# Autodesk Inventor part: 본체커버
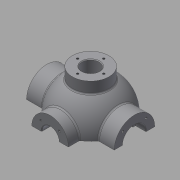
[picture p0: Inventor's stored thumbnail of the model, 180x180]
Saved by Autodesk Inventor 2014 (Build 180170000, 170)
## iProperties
Created: 2015-12
Part Number: 본체커버
Material: 알루미늄 6061
Document SubType Name: Modeling
Designer: mduedu
Density: 1 g/cm^3
Mass: 574.351 g
Surface Area: 450.515 cm^2
Volume: 211.938 cm^3
Appearance: 알루미늄 - 평지
Author: mduedu
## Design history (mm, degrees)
sketch "스케치1"
  geometry: L1 (-53, 0)-(53, 0); A1 r 53 centre (0, 0) between (53, 0) and (-53, 0); 2 further points
  constraints: 2 coincident, 2 end point, 2 point on circle, 1 centre point, 1 horizontal, 1 midpoint
  dimensions: "d0" = 53 radius of A1
revolve "회전1" sketch "스케치1" stored, may be unused: angle "d2" = 90 deg
feature "쉘1" dims "d11" = 10
node "작업 평면1"
sketch "스케치2"
  geometry: C1 r 31 at (0, 0); 1 further point
  constraints: 1 centre point, 1 coincident
  dimensions: "d4" = 62 diameter of C1
extrude "돌출1" join sketch "스케치2" stored distance "d5" = 10; taper "d6" = 0 deg
node "작업 평면2"
sketch "스케치3"
  geometry: C1 r 28 at (0, 0); 1 further point
  constraints: 1 centre point, 1 coincident
  dimensions: "d8" = 56 diameter of C1
extrude "돌출2" join sketch "스케치3" stored distance "d9" = 10; taper "d10" = 0 deg
hole "구멍1" diameter "d14" = 35; stored, may be unused: countersink angle "d18" = 90 deg, drill point angle "d20" = 0 deg; dims "d12" = 10, "d13" = 10, "d15" = 6, "d16" = 4, "d17" = 2, "d19" = 16
hole "구멍2" diameter "d23" = 27; stored, may be unused: countersink angle "d27" = 90 deg, drill point angle "d29" = 0 deg; dims "d21" = 10, "d22" = 10, "d24" = 6, "d25" = 4, "d26" = 2, "d28" = 16
fillet "모깎기1" dims "d30" = 0.3
hole "구멍3" diameter "d33" = 26; stored, may be unused: countersink angle "d37" = 90 deg, drill point angle "d39" = 0 deg; dims "d31" = 10, "d32" = 10, "d34" = 6, "d35" = 4, "d36" = 2, "d38" = 16
chamfer "모따기1" distance "d40" = 1; stored, may be unused: second distance "d41" = 2, angle "d42" = 45 deg
sketch "스케치4"
  geometry: L1 (0, 0)-(0, -25); L2 (0, 0)-(-17.678, -17.678); A1 r 25 centre (0, 0) between (-17.678, -17.678) and (0, -25); 1 further point
  constraints: 4 end point, 2 point on circle, 1 centre point, 1 coincident, 1 vertical
  dimensions: "d43" = 50 diameter of A1; "d47" = 45 deg angle of L1 L2
hole "구멍4" sketch "스케치4" at (-17.678, -17.678) diameter "d49" = 3.242; stored, may be unused: countersink angle "d53" = 90 deg, drill point angle "d55" = 118 deg; dims "d50" = 11, "d51" = 4, "d52" = 2, "d54" = 13
sketch "스케치5"
  geometry: L1 (0, 0)-(0, -20); L2 (0, 0)-(-14.142, -14.142); A1 r 20 centre (0, 0) between (0, -20) and (-14.142, -14.142); 2 further points
  constraints: 4 end point, 2 coincident, 2 point on circle, 1 centre point, 1 vertical
  dimensions: "d59" = 40 diameter of A1; "d65" = 45 deg angle of L1 L2
hole "구멍5" sketch "스케치5" at (-14.142, -14.142) diameter "d67" = 3.242; stored, may be unused: countersink angle "d71" = 90 deg, drill point angle "d73" = 118 deg; dims "d68" = 8, "d69" = 4, "d70" = 2, "d72" = 10
node "작업 평면3"
sketch "스케치6"
  geometry: C1 r 65 at (0, 0); 1 further point
  constraints: 1 centre point, 1 coincident
  dimensions: "d78" = 130 diameter of C1
extrude "돌출3" join sketch "스케치6" distance "d80" = 10; taper "d81" = 0 deg
sketch "스케치7"
  geometry: C1 r 20 at (0, 0); 1 further point
  constraints: 1 centre point, 1 coincident
  dimensions: "d82" = 40 diameter of C1
extrude "돌출4" join sketch "스케치7" stored distance "d84" = 10; taper "d85" = 0 deg
sketch "스케치8"
  geometry: 2 further points
  constraints: 1 coincident
hole "구멍6" sketch "스케치8" at (0, 0) diameter "d86" = 20; stored, may be unused: countersink angle "d90" = 90 deg, drill point angle "d92" = 118 deg; dims "d87" = 7, "d88" = 40, "d89" = 5, "d91" = 10
fillet "모깎기2" dims "d93" = 0.3
sketch "스케치9"
  geometry: L1 (65, -75)-(-65, -75) reference; L2 (-45, -75)-(-38.245, -36.692); A1 r 53 centre (0, 0) between (42.988, 31) and (42.988, -31) reference; 1 further point
  constraints: 2 end point, 1 point on circle, 1 point on line
  dimensions: "d94" = 45 horizontal distance of L2.start point (0, 0); "d95" = 80 deg angle of L2 L1
feature "리브1" sketch "스케치9" dims "d96" = 1, "d97" = 8, "d98" = 0, "d99" = 0, "d100" = 1, "d101" = 1
sketch "스케치10"
  geometry: L1 (0, 0)-(0, -55); L2 (0, 0)-(-38.891, -38.891); A1 r 55 centre (0, 0) between (0, -55) and (-38.891, -38.891); 2 further points
  constraints: 4 end point, 2 coincident, 2 point on circle, 1 centre point, 1 vertical
  dimensions: "d105" = 110 diameter of A1; "d107" = 45 deg angle of L1 L2
hole "구멍7" sketch "스케치10" at (-38.891, -38.891) diameter "d109" = 10; stored, may be unused: countersink angle "d113" = 90 deg, drill point angle "d115" = 118 deg; dims "d110" = 7, "d111" = 40, "d112" = 5, "d114" = 10
fillet "모깎기3" dims "d120" = 3
fillet "모깎기4" dims "d121" = 3, "d122" = 3
fillet "모깎기5" dims "d123" = 3
fillet "모깎기6" dims "d124" = 3
sketch "스케치11"
  geometry: C1 r 5 at (-38.891, 38.891) reference; C2 r 5 at (38.891, 38.891) reference; C3 r 5 at (38.891, -38.891) reference; C4 r 5 at (-38.891, -38.891) reference; C5 r 20 at (0, 0) reference; C6 r 65 at (0, 0) reference; 1 further point
  constraints: 3 other
feature "엠보싱1" sketch "스케치11" dims "d125" = 0.5, "d126" = 0
sketch "스케치12"
  geometry: L1 (0, 100)-(0, -100); L2 (0, 100)-(-150, 100); L3 (-150, 100)-(-150, -100); L4 (-150, -100)-(0, -100); 2 further points
  constraints: 8 end point, 3 perpendicular, 1 coincident, 1 midpoint, 1 vertical
  dimensions: "d127" = 200 distance of L2.end L3.end; "d129" = 150 distance of L3.end L1.end
extrude "돌출5" cut sketch "스케치12" stored distance "d130" = 10; taper "d131" = 0 deg
sketch "스케치13"
  geometry: C1 r 7 at (0, -53); A1 r 53 centre (0, 0) between (-42.113, -32.179) and (42.113, -32.179) reference; 1 further point
  constraints: 1 centre point, 1 point on circle
  dimensions: "d132" = 14 diameter of C1
extrude "돌출6" join sketch "스케치13" distance "d133" = 5; taper "d134" = 0 deg
sketch "스케치14"
  geometry: C1 r 7 at (0, 0) reference; 1 further point
extrude "돌출7" cut sketch "스케치14" stored distance "d135" = 5; taper "d136" = 0 deg
sketch "스케치15"
  geometry: C1 r 2.25 at (0, 53); A1 r 7 centre (0, 53) between (6.965, 52.302) and (-6.965, 52.302) reference; 1 further point
  constraints: 1 centre point, 1 coincident
  dimensions: "d139" = 4.5 diameter of C1
extrude "돌출8" cut sketch "스케치15" stored distance "d141" = 5; taper "d142" = 0 deg
fillet "모깎기7" dims "d143" = 3
fillet "모깎기8" dims "d144" = 1
fillet "모깎기9" dims "d145" = 1
fillet "모깎기10" dims "d146" = 1
node "작업 평면4"
sketch "스케치16"
  geometry: C1 r 28 at (0, 0); 1 further point
  constraints: 1 centre point, 1 coincident
  dimensions: "d148" = 56 diameter of C1
extrude "돌출9" join sketch "스케치16" stored distance "d150" = 5; taper "d151" = 0 deg
hole "구멍8" diameter "d154" = 26; stored, may be unused: countersink angle "d158" = 90 deg, drill point angle "d160" = 118 deg; dims "d152" = 10, "d153" = 10, "d155" = 6, "d156" = 4, "d157" = 2, "d159" = 8
sketch "스케치17" dims "d161" = 40
  geometry: 3 further points
  constraints: 2 vertical alignment, 1 coincident, 2 other
hole "구멍9" sketch "스케치17" at (0, 20) diameter "d163" = 3.242; stored, may be unused: countersink angle "d167" = 90 deg, drill point angle "d169" = 118 deg; dims "d164" = 8, "d165" = 4, "d166" = 2, "d168" = 10
fillet "모깎기11" dims "d173" = 3
chamfer "모따기2" distance "d174" = 1; stored, may be unused: second distance "d175" = 2, angle "d176" = 45 deg
node "솔리드1"
mirror "대칭1"
mirror "대칭2"
pattern_circular "원형 패턴1" dims angle "d57" = 360 deg
mirror "대칭3"
pattern_circular "원형 패턴2" dims angle "d75" = 360 deg
pattern_circular "원형 패턴3" dims angle "d103" = 360 deg
pattern_circular "원형 패턴4" dims angle "d118" = 360 deg
pattern_circular "원형 패턴5" dims angle "d171" = 360 deg
node "투영된 루프1"
other parameters: "d3" = 67, "d7" = 62, "d77" = -85, "d147" = 62
